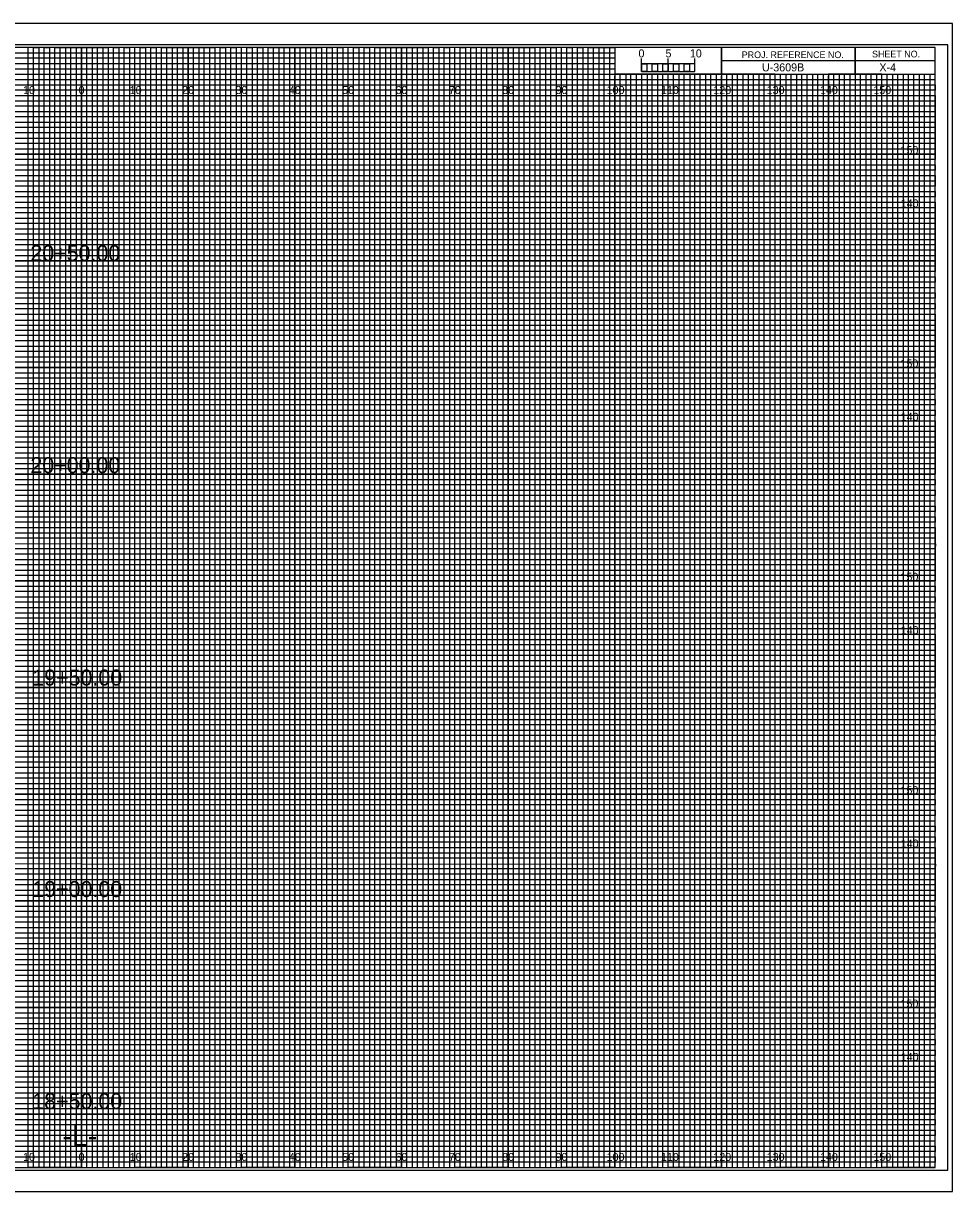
# Model space of a CAD drawing. Extents: x -13 to 329, y -17 to 10994.
# Drawn here: x 149.1 to 323.3, y 435.5 to 654.5 of the extents above; entities that cross this region are included whole.
import ezdxf

# ---------------------------------------------------------------- set-up
doc = ezdxf.new("R2010")
doc.units = 0
for name, color, linetype in [('Prop XS Alignment Label', 7, 'Continuous'), ('Prop XS Bar Scale Labels', 7, 'Continuous'), ('Prop XS Elevation Labels', 7, 'Continuous'), ('Prop XS Offset Labels', 7, 'Continuous'), ('Prop XS Project Number', 7, 'Continuous'), ('Prop XS Sheet Number', 7, 'Continuous'), ('Prop XS Station Labels', 7, 'Continuous'), ('Sheet Cross Section CELL', 7, 'Continuous'), ('Sheet Cross Section Grid Major CELL', 7, 'Continuous'), ('Sheet Cross Section Grid Middle CELL', 7, 'Continuous'), ('Sheet Cross Section Grid Minor 1 CELL', 7, 'Continuous'), ('Sheet Cross Section Grid Minor 2 CELL', 7, 'Continuous'), ('Sheet Cross Section Scale CELL', 7, 'Continuous'), ('Sheet Cutting Line CELL', 7, 'Continuous'), ('Sheet DOT Grid CELL', 7, 'Continuous'), ('Sheet Plot Border Inside CELL', 7, 'Continuous'), ('Sheet Plot Border Outside CELL', 7, 'Continuous')]:
    doc.layers.add(name, color=color, linetype=linetype)

msp = doc.modelspace()

# ---------------------------------------------------------------- linework, layer by layer
at = {"layer": 'Sheet Cross Section CELL'}
for p, q in [((305, 650), (305, 645)), ((305, 645), (305, 650)), ((280, 647.5), (280, 645)), ((320, 647.49), (280, 647.49)), ((280, 645), (320, 645))]:
    msp.add_line(p, q, dxfattribs=at)
for points in [[(320, 650), (0, 650), (0, 440), (320, 440)], [(280, 650), (260, 650), (260, 645.03), (280, 645.03)], [(320, 650), (280, 650), (280, 645), (320, 645)]]:
    msp.add_lwpolyline(points, close=True, dxfattribs=at)
at = {"layer": 'Sheet Cross Section Grid Major CELL'}
for p, q in [((150, 650), (140, 650)), ((150, 440), (150, 650)), ((170, 650), (160, 650)), ((160, 650), (160, 440)), ((170, 440), (170, 650)), ((190, 650), (180, 650)), ((180, 650), (180, 440)), ((190, 440), (190, 650)), ((210, 650), (200, 650)), ((200, 650), (200, 440)), ((210, 440), (210, 650)), ((230, 650), (220, 650)), ((220, 650), (220, 440)), ((230, 440), (230, 650)), ((250, 650), (240, 650)), ((240, 650), (240, 440)), ((250, 440), (250, 650)), ((260, 650), (260, 440)), ((270, 440), (270, 645)), ((290, 645), (280, 645)), ((280, 645), (280, 440)), ((290, 440), (290, 645)), ((310, 645), (300, 645)), ((300, 645), (300, 440)), ((310, 440), (310, 645)), ((160, 440), (150, 440)), ((180, 440), (170, 440)), ((200, 440), (190, 440)), ((220, 440), (210, 440)), ((240, 440), (230, 440)), ((260, 440), (250, 440)), ((280, 440), (270, 440)), ((300, 440), (290, 440)), ((320, 440), (310, 440)), ((320, 440), (320, 440))]:
    msp.add_line(p, q, dxfattribs=at)
for points in [[(0, 640), (320, 640), (320, 630), (0, 630)], [(0, 620), (320, 620), (320, 610), (0, 610)], [(0, 600), (320, 600), (320, 590), (0, 590)], [(0, 580), (320, 580), (320, 570), (0, 570)], [(0, 560), (320, 560), (320, 550), (0, 550)], [(0, 540), (320, 540), (320, 530), (0, 530)], [(0, 520), (320, 520), (320, 510), (0, 510)], [(0, 500), (320, 500), (320, 490), (0, 490)], [(0, 480), (320, 480), (320, 470), (0, 470)], [(0, 460), (320, 460), (320, 450), (0, 450)]]:
    msp.add_lwpolyline(points, dxfattribs=at)
at = {"layer": 'Sheet Cross Section Grid Middle CELL'}
for points in [[(145, 440), (155, 440), (155, 650), (165, 650), (165, 440), (175, 440), (175, 650), (185, 650), (185, 440), (195, 440), (195, 650), (205, 650), (205, 440), (215, 440), (215, 650), (225, 650), (225, 440), (235, 440), (235, 650), (245, 650), (245, 440), (255, 440), (255, 650), (259.93, 650), (260, 650), (260, 645), (264.99, 645), (264.99, 440), (275, 440), (275, 645), (285, 645), (285, 440), (295, 440), (295, 645), (305, 645), (305, 440), (315, 440), (315, 645)], [(0, 645), (275, 645)], [(0, 625), (320, 625), (320, 635), (0, 635)], [(0, 605), (320, 605), (320, 615), (0, 615)], [(0, 585), (320, 585), (320, 595), (0, 595)], [(0, 565), (320, 565), (320, 575), (0, 575)], [(0, 545), (320, 545), (320, 555), (0, 555)], [(0, 525), (320, 525), (320, 535), (0, 535)], [(0, 505), (320, 505), (320, 515), (0, 515)], [(0, 485), (320, 485), (320, 495), (0, 495)], [(0, 465), (320, 465), (320, 475), (0, 475)], [(0, 445), (320, 445), (320, 455), (0, 455)]]:
    msp.add_lwpolyline(points, dxfattribs=at)
at = {"layer": 'Sheet Cross Section Grid Minor 1 CELL'}
for p, q in [((0, 649), (260, 649)), ((260, 649), (260, 647.98)), ((260, 647.98), (0, 647.98)), ((0, 647), (260, 647)), ((260, 647), (260, 645.89)), ((260, 645.89), (0, 645.89)), ((0, 644), (320, 644))]:
    msp.add_line(p, q, dxfattribs=at)
for points in [[(0, 643), (270, 643), (320, 643), (320, 642), (0, 642)], [(0, 641), (320, 641), (320, 639), (0, 639)], [(0, 638), (320, 638), (320, 637), (0, 636.98)], [(0, 636), (320, 636), (320, 634), (0, 634)], [(0, 633), (320, 633), (320, 632), (0, 632)], [(0, 631), (320, 631), (320, 629), (0, 629)], [(0, 628), (320, 628), (320, 627), (0, 627)], [(0, 626), (320, 626), (320, 624), (0, 624)], [(0, 623), (320, 623), (320, 622), (0, 622)], [(0, 621), (320, 621), (320, 619), (0, 619)], [(0, 618), (320, 618), (320, 617), (0, 617)], [(0, 616), (320, 616), (320, 613.95), (320, 613), (320, 612), (0, 612)], [(0, 614), (320, 614), (320, 613), (0, 613)], [(0, 611), (320, 611), (320, 609), (0, 609.03)], [(0, 609.03), (320, 609), (320, 608), (0, 608)], [(0, 607), (320, 607), (320, 606), (0, 606)], [(0, 604), (320, 604), (320, 603), (0, 603)], [(0, 602), (320, 602), (320, 601), (0, 601)], [(-0.07, 598.89), (320, 598.89), (320, 597.88), (-0.07, 597.88)], [(0, 597), (320, 597), (320, 596), (0, 596)], [(0, 594), (320, 594), (320, 593), (0, 593)], [(0, 592), (320, 592), (320, 591), (0, 591)], [(0, 589), (320, 589), (320, 588), (0, 588)], [(0, 587), (320, 587), (320, 586), (0, 586)], [(0, 584), (320, 584), (320, 583), (0, 583)], [(0, 582), (320, 582), (320, 581), (0, 581)], [(0, 579), (320, 579), (319.99, 577.98), (0, 578)], [(0, 577), (320, 577), (320, 576), (0, 576)], [(0, 574), (320, 574), (320, 573), (0, 573)], [(0, 572), (320, 572), (320, 571), (0, 571)], [(0, 569), (320, 569), (320, 568), (0, 568)], [(0, 567), (320, 567), (320, 566), (0, 566)], [(0, 564), (320, 564), (320, 563), (0, 563)], [(0, 562), (320, 562), (320, 561), (0, 561)], [(0, 559), (320, 559), (320, 558), (0, 558)], [(0, 556.99), (320.07, 556.91), (320, 556), (0, 556)], [(0, 554), (320, 554), (320, 553), (0, 553)], [(0, 552), (320, 552), (320, 551), (0, 551)], [(0, 549), (320, 549), (320, 548), (0, 548)], [(0, 547), (320, 547), (320, 546), (0, 546)], [(0, 544), (320, 544), (320, 543), (0, 543)], [(0, 542), (320, 542), (320, 541), (0, 541)], [(0, 539), (320, 539), (320, 538), (0, 538)], [(0, 537), (320, 537), (320, 536), (0, 536)], [(0, 534), (320, 534), (320, 533), (0, 533)], [(0, 532), (320, 532), (320, 531), (0, 531)], [(0, 529), (320, 529), (320, 528), (0, 528)], [(0, 527), (320, 527), (320, 526), (0, 526)], [(0, 524), (320, 524), (320, 523), (0, 523)], [(0, 522), (320, 522), (320, 521), (0, 521)], [(0, 519), (320, 519), (319.99, 517.98), (0, 518)], [(0, 517), (320, 517), (320, 516), (0, 516)], [(0, 514), (320, 514), (320, 513), (0, 513)], [(0, 512), (320, 512), (320, 511), (0, 511)], [(0, 509), (320, 509), (320, 508), (0, 508)], [(0, 507), (320, 507), (320, 506), (0, 506)], [(0, 504), (320, 504), (320, 503), (0, 503)], [(0, 502), (320, 502), (320, 501), (0, 501)], [(0, 499), (320, 499), (320, 498), (0, 498)], [(0, 496.99), (320.07, 496.91), (320, 496), (0, 496)], [(0, 494), (320, 494), (320, 493), (0, 493)], [(0, 492), (320, 492), (320, 491), (0, 491)], [(0, 489), (320, 489), (320, 488), (0, 488)], [(0, 487), (320, 487), (320, 486), (0, 486)], [(0, 484), (320, 484), (320, 483), (0, 483)], [(0, 482), (320, 482), (320, 481), (0, 481)], [(0, 479), (320, 479), (320, 478), (0, 478)], [(0, 477), (320, 477), (320, 476), (0, 476)], [(0, 474), (320, 474), (320, 473), (0, 473)], [(0, 472), (320, 472), (320, 471), (0, 471)], [(0, 469), (320, 469), (320, 468), (0, 468)], [(0, 467), (320, 467), (320, 466), (0, 466)], [(0, 464), (320, 464), (320, 463), (0, 463)], [(0, 462), (320, 462), (320, 461), (0, 461)], [(0, 459), (320, 459), (320, 458), (0, 458)], [(0, 457), (320, 457), (320, 456), (0, 456)], [(0, 454), (320, 454), (320, 453), (0, 453)], [(0, 452), (320, 452), (320, 451), (0, 451)], [(0, 449), (320, 449), (320, 448), (0, 448)], [(0, 447), (320, 447), (320, 446), (0, 446)], [(0, 444), (320, 444), (320, 443), (0, 443)], [(0, 442), (320, 442), (320, 441), (0, 441)]]:
    msp.add_lwpolyline(points, dxfattribs=at)
at = {"layer": 'Sheet Cross Section Grid Minor 2 CELL'}
for p, q in [((267, 645), (266.01, 645)), ((266.01, 645), (266.01, 440)), ((267, 440), (267, 645)), ((269, 645), (268, 645)), ((268, 645), (268, 440)), ((269, 440), (269, 645)), ((266.01, 440), (265, 440)), ((268, 440), (267, 440))]:
    msp.add_line(p, q, dxfattribs=at)
for points in [[(150, 440), (151, 440), (151, 650), (152, 650), (152, 440)], [(152, 440), (153, 440), (153, 650), (154, 650), (154, 440)], [(155, 440), (156, 440), (156, 650), (157, 650), (157, 440)], [(157, 440), (158, 440), (158, 650), (159, 650), (159, 440)], [(160, 440), (161, 440), (161, 650), (162, 650), (162, 440)], [(162, 440), (163, 440), (163, 650), (164, 650), (164, 440)], [(165, 440), (166, 440), (166, 650), (167, 650), (167, 440)], [(167, 440), (168, 440), (168, 650), (169, 650), (169, 440)], [(170, 440), (171, 440), (171, 650), (172, 650), (172, 440)], [(172, 440), (173, 440), (173, 650), (174, 650), (174, 440)], [(175, 440), (176, 440), (176, 650), (177, 650), (177, 440)], [(177, 440), (178, 440), (178, 650), (179, 650), (179, 440)], [(180, 440), (181, 440), (181, 650), (182, 650), (182, 440)], [(182, 440), (183, 440), (183, 650), (184, 650), (184, 440)], [(185, 440), (186, 440), (186, 650), (187, 650), (187, 440)], [(187, 440), (188, 440), (188, 650), (189, 650), (189, 440)], [(190, 440), (191, 440), (191, 650), (192, 650), (192, 440)], [(192, 440), (193, 440), (193, 650), (194, 650), (194, 440)], [(195, 440), (196, 440), (196, 650), (197, 650), (197, 440)], [(197, 440), (198, 440), (198, 650), (199, 650), (199, 440)], [(200, 440), (201, 440), (201, 650), (202, 650), (202, 440)], [(202, 440), (203, 440), (203, 650), (204, 650), (204, 440)], [(205, 440), (206, 440), (206, 650), (207, 650), (207, 440)], [(207, 440), (208, 440), (208, 650), (209, 650), (209, 440)], [(210, 440), (211, 440), (211, 650), (212, 650), (212, 440)], [(212, 440), (213, 440), (213, 650), (214, 650), (214, 440)], [(215, 440), (216, 440), (216, 650), (217, 650), (217, 440)], [(217, 440), (218, 440), (218, 650), (219, 650), (219, 440)], [(220, 440), (221, 440), (221, 650), (222, 650), (222, 440)], [(222, 440), (223, 440), (223, 650), (224, 650), (224, 440)], [(225, 440), (226, 440), (226, 650), (227, 650), (227, 440)], [(227, 440), (228, 440), (228, 650), (229, 650), (229, 440)], [(230, 440), (231, 440), (231, 650), (232, 650), (232, 440)], [(232, 440), (233, 440), (233, 650), (234, 650), (234, 440)], [(235, 440), (236, 440), (236, 650), (237, 650), (237, 440)], [(237, 440), (238, 440), (238, 650), (239, 650), (239, 440)], [(240, 440), (241, 440), (241, 650), (242, 650), (242, 440)], [(242, 440), (243, 440), (243, 650), (244, 650), (244, 440)], [(245, 440), (246, 440), (246, 650), (247, 650), (247, 440)], [(247, 440), (248, 440), (248, 650), (249, 650), (249, 440)], [(250, 440), (251, 440), (251, 650), (252, 650), (252, 440)], [(252, 440), (253, 440), (253, 650), (254, 650), (254, 440)], [(255, 440), (256, 440), (256, 650), (257, 650), (257, 440)], [(257, 440), (258, 440), (258, 650), (259, 650), (259, 440)], [(260, 440), (261, 440), (261, 645), (262.02, 645), (262.02, 440)], [(262, 440), (263, 440), (263, 645), (263.99, 645), (263.99, 440)], [(270, 440), (270.98, 440), (270.98, 645), (272, 645), (272, 440)], [(272, 440), (273, 440), (273, 645), (274.05, 645), (274.05, 440)], [(275, 440), (276, 440), (276, 645), (277, 645), (277, 440)], [(277, 440), (278, 440), (278, 645), (279, 645), (279, 440)], [(280, 440), (281, 440), (281, 645), (282, 645), (282, 440)], [(282, 440), (283, 440), (283, 645), (284, 645), (284, 440)], [(285, 440), (286, 440), (286, 645), (287, 645), (287, 440)], [(287, 440), (288, 440), (288, 645), (289, 645), (289, 440)], [(290, 440), (291, 440), (291, 645), (292, 645), (292, 440)], [(292, 440), (293, 440), (293, 645), (294, 645), (294, 440)], [(295, 440), (296, 440), (296, 645), (297, 645), (297, 440)], [(297, 440), (298, 440), (298, 645), (299, 645), (299, 440)], [(300, 440), (301, 440), (301, 645), (302, 645), (302, 440)], [(302, 440), (303, 440), (303, 645), (304, 645), (304, 440)], [(305, 440), (306, 440), (306, 645), (307, 645), (307, 440)], [(307, 440), (308, 440), (308, 645), (309, 645), (309, 440)], [(310, 440), (311, 440), (311, 645), (312, 645), (312, 440)], [(312, 440), (313, 440), (313, 645), (314, 645), (314, 440)], [(315, 440), (316, 440), (316, 645), (317, 645), (317, 440)], [(317, 440), (318, 440), (318, 645), (319, 645), (319, 440)]]:
    msp.add_lwpolyline(points, dxfattribs=at)
at = {"layer": 'Sheet Cross Section Scale CELL'}
for p, q in [((265, 645.49), (265, 647.9)), ((265, 646.9), (265, 647.9)), ((270, 645.49), (270, 647.9)), ((275, 645.49), (275, 647.9)), ((275, 646.9), (275, 647.9))]:
    msp.add_line(p, q, dxfattribs=at)
for points in [[(275, 646.9), (265, 646.9), (265, 645.49), (275, 645.49)], [(265, 646.9), (266, 646.9), (266, 645.49), (265, 645.49)], [(267, 646.9), (268, 646.9), (268, 645.49), (267, 645.49)], [(269, 646.9), (270, 646.9), (270, 645.49), (269, 645.49)], [(271, 646.9), (272, 646.9), (272, 645.49), (271, 645.49)], [(273, 646.9), (274, 646.9), (274, 645.49), (273, 645.49)]]:
    msp.add_lwpolyline(points, close=True, dxfattribs=at)
at = {"layer": 'Sheet Cutting Line CELL'}
for p, q in [((323.3, 654.5), (-13.4, 654.5)), ((-13.4, 435.5), (323.3, 435.5))]:
    msp.add_line(p, q, dxfattribs=at)
at = {"layer": 'Sheet DOT Grid CELL'}
for p, q in [((150, 440), (150, 650)), ((160, 440), (160, 650)), ((170, 440), (170, 650)), ((180, 440), (180, 650)), ((190, 440), (190, 650)), ((200, 440), (200, 650)), ((210, 440), (210, 650)), ((220, 440), (220, 650)), ((230, 440), (230, 650)), ((240, 440), (240, 650)), ((250, 440), (250, 650)), ((260, 440), (260, 644.69)), ((270, 440), (270, 644.69)), ((280, 440), (280, 644.69)), ((290, 440), (290, 644.69)), ((300, 440), (300, 644.69)), ((310, 440), (310, 644.69)), ((0, 640), (320, 640)), ((0, 630), (320, 630)), ((0, 620), (320, 620)), ((0, 610), (320, 610)), ((0, 600), (320, 600)), ((0, 590), (320, 590)), ((0, 580), (320, 580)), ((0, 570), (320, 570)), ((0, 560), (320, 560)), ((0, 550), (320, 550)), ((0, 540), (320, 540)), ((0, 530), (320, 530)), ((0, 520), (320, 520)), ((0, 510), (320, 510)), ((0, 500), (320, 500)), ((0, 490), (320, 490)), ((0, 480), (320, 480)), ((0, 470), (320, 470)), ((0, 460), (320, 460)), ((0, 450), (320, 450))]:
    msp.add_line(p, q, dxfattribs=at)
at = {"layer": 'Sheet Plot Border Inside CELL'}
msp.add_lwpolyline([(-10.8, 439.5), (322.4, 439.5), (322.4, 650.5), (-10.8, 650.5)], close=True, dxfattribs=at)
at = {"layer": 'Sheet Plot Border Outside CELL'}
msp.add_lwpolyline([(-13.4, 435.5), (323.3, 435.5), (323.3, 654.5), (-13.4, 654.5)], close=True, dxfattribs=at)

# ---------------------------------------------------------------- texts
at = {"layer": 'Prop XS Alignment Label'}
msp.add_text('-L-', height=4, dxfattribs=at).set_placement((156.42, 444))
at = {"layer": 'Prop XS Bar Scale Labels'}
for s, p in [('5', (269.47, 648.12)), ('10', (274.04, 648.12))]:
    msp.add_text(s, height=1.5, dxfattribs=at).set_placement(p)
at = {"layer": 'Prop XS Elevation Labels'}
for s, p in [('150', (313.52, 630)), ('140', (313.57, 620)), ('150', (313.52, 590)), ('140', (313.57, 580)), ('150', (313.52, 550)), ('140', (313.57, 540)), ('150', (313.52, 510)), ('140', (313.57, 500)), ('150', (313.52, 470)), ('140', (313.57, 460))]:
    msp.add_text(s, height=1.5, dxfattribs=at).set_placement(p)
at = {"layer": 'Prop XS Offset Labels'}
for s, p in [('10', (149.04, 641.25)), ('0', (159.45, 641.25)), ('0', (159.45, 641.25)), ('10', (169.04, 641.25)), ('20', (178.86, 641.25)), ('30', (188.86, 641.25)), ('40', (198.86, 641.25)), ('50', (208.86, 641.25)), ('60', (218.86, 641.25)), ('70', (228.86, 641.25)), ('80', (238.86, 641.25)), ('90', (248.86, 641.25)), ('100', (258.44, 641.25)), ('110', (268.62, 641.25)), ('120', (278.44, 641.25)), ('130', (288.44, 641.25)), ('140', (298.44, 641.25)), ('150', (308.44, 641.25)), ('10', (149.04, 441.25)), ('0', (159.45, 441.25)), ('0', (159.45, 441.25)), ('10', (169.04, 441.25)), ('20', (178.86, 441.25)), ('30', (188.86, 441.25)), ('40', (198.86, 441.25)), ('50', (208.86, 441.25)), ('60', (218.86, 441.25)), ('70', (228.86, 441.25)), ('80', (238.86, 441.25)), ('90', (248.86, 441.25)), ('100', (258.44, 441.25)), ('110', (268.62, 441.25)), ('120', (278.44, 441.25)), ('130', (288.44, 441.25)), ('140', (298.44, 441.25)), ('150', (308.44, 441.25))]:
    msp.add_text(s, height=1.5, dxfattribs=at).set_placement(p)
at = {"layer": 'Prop XS Project Number'}
msp.add_text('U-3609B', height=1.5, dxfattribs=at).set_placement((287.56, 645.5))
at = {"layer": 'Prop XS Sheet Number'}
msp.add_text('X-4', height=1.5, dxfattribs=at).set_placement((309.57, 645.5))
at = {"layer": 'Prop XS Station Labels'}
for s, p in [('20+50.00', (150.41, 609.94)), ('20+00.00', (150.41, 570.19)), ('19+50.00', (150.77, 530.37)), ('19+00.00', (150.77, 490.72)), ('18+50.00', (150.77, 450.96))]:
    msp.add_text(s, height=3, dxfattribs=at).set_placement(p)
at = {"layer": 'Sheet Cross Section CELL'}
for s, p in [('PROJ. REFERENCE NO.', (283.77, 647.99)), ('SHEET NO.', (308.19, 648.12))]:
    msp.add_text(s, height=1.25, dxfattribs=at).set_placement(p)
at = {"layer": 'Sheet Cross Section Scale CELL'}
msp.add_text('0', height=1.5, dxfattribs=at).set_placement((264.41, 648.12))

doc.saveas('drawing.dxf')
